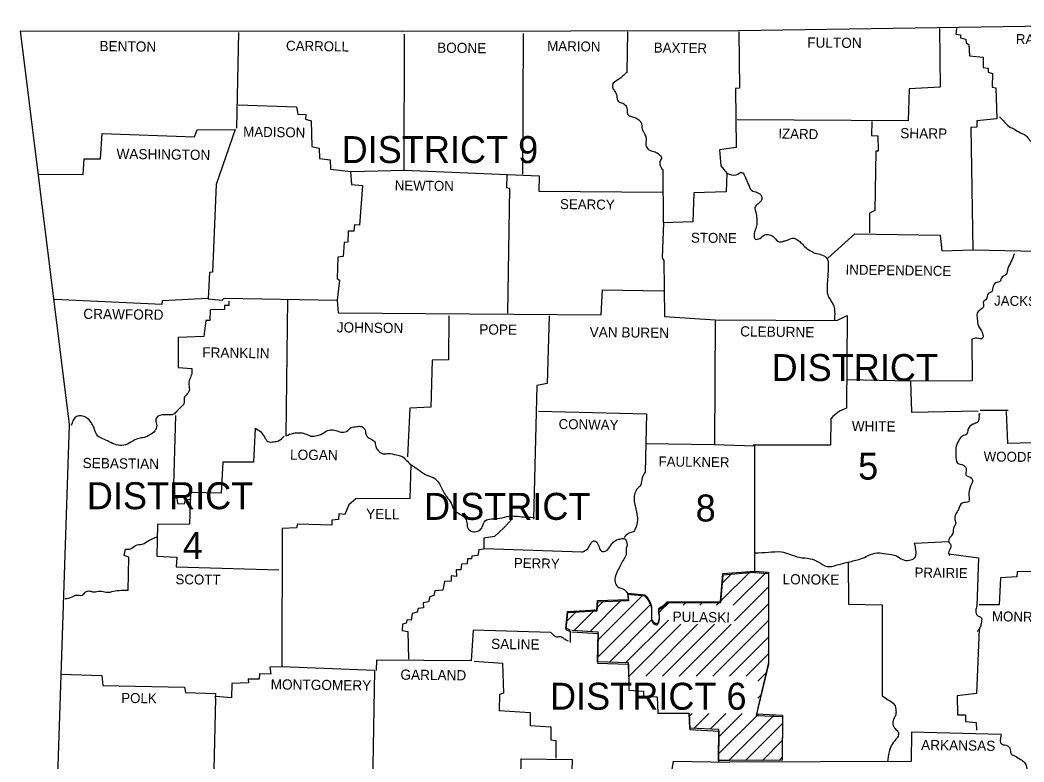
# Model space of a CAD drawing. Extents: x 76 to 6945, y -3933 to 2152.
# Drawn here: x 5012.1 to 5436, y -2002.1 to -1688.7 of the extents above; entities that cross this region are included whole.
import ezdxf

# ---------------------------------------------------------------- set-up
doc = ezdxf.new("R2010")
doc.units = 0
doc.layers.add('R_Draft', color=7, linetype='Continuous')

msp = doc.modelspace()

# ---------------------------------------------------------------- linework, layer by layer
at = {"layer": 'R_Draft'}
for p, q in [((5417.49, -1853.41), (5429.39, -1853.41)), ((5161.79, -1963.41), (5160.63, -2026.21))]:
    msp.add_line(p, q, dxfattribs=at)
for points in [[(5012.09, -1693.31), (5173.79, -1693.41), (5315.69, -1693.11), (5483.09, -1690.51), (5560.69, -1688.71)], [(5012.09, -1693.31), (5032.79, -1859.51), (5023.79, -2130.81)], [(5104.39, -1693.91), (5103.49, -1734.41)], [(5104.19, -1724.51), (5128.79, -1725.31), (5129.39, -1728.51), (5132.79, -1728.61), (5132.69, -1730.61), (5135.09, -1731.21), (5135.29, -1742.11), (5138.39, -1742.81), (5138.59, -1747.11), (5142.99, -1747.71), (5143.19, -1751.71), (5151.89, -1752.61), (5174.29, -1752.11), (5174.49, -1694.61)], [(5224.59, -1694.41), (5224.29, -1753.81)], [(5268.59, -1693.71), (5268.39, -1710.81)], [(5315.69, -1693.71), (5315.89, -1717.51), (5314.19, -1717.61), (5314.49, -1742.51), (5307.49, -1743.51), (5308.09, -1750.21), (5310.49, -1753.31), (5310.29, -1761.21), (5296.69, -1761.71), (5296.19, -1773.91), (5283.79, -1774.31), (5283.19, -1789.11), (5283.89, -1790.31), (5284.19, -1813.91), (5305.59, -1815.31), (5305.29, -1868.01), (5322.29, -1868.51), (5322.29, -1922.11), (5308.89, -1923.11), (5307.89, -1934.91), (5285.39, -1935.01)], [(5400.39, -1692.21), (5400.59, -1717.01), (5387.59, -1717.71), (5387.19, -1731.31), (5314.89, -1730.91)], [(5407.59, -1692.31), (5407.29, -1694.71), (5409.29, -1695.01), (5409.19, -1696.21), (5411.49, -1696.71), (5411.69, -1698.31), (5412.79, -1699.01), (5413.09, -1703.81), (5418.79, -1704.41), (5418.79, -1708.71), (5420.89, -1709.01), (5420.89, -1710.71), (5422.69, -1711.21), (5422.59, -1717.01), (5424.19, -1717.31), (5424.59, -1730.41), (5416.09, -1731.21), (5416.19, -1734.01), (5413.59, -1734.11), (5414.49, -1785.71), (5454.79, -1786.61), (5455.49, -1866.81), (5429.19, -1867.51), (5428.69, -1854.01)], [(5371.79, -1731.61), (5371.59, -1737.41), (5374.39, -1737.61), (5374.49, -1744.01), (5373.49, -1744.01), (5373.09, -1769.21), (5370.79, -1770.21), (5370.79, -1778.61)], [(5019.99, -1753.81), (5038.69, -1753.91), (5039.19, -1747.31), (5046.09, -1747.31), (5046.69, -1736.61), (5085.69, -1738.01), (5086.89, -1735.01), (5102.99, -1734.91), (5094.89, -1758.11), (5093.29, -1795.21), (5092.09, -1795.31), (5091.49, -1806.51), (5097.39, -1807.01), (5098.29, -1806.11), (5145.99, -1807.01), (5146.49, -1812.31)], [(5151.69, -1752.81), (5152.09, -1758.21), (5156.69, -1758.51), (5155.49, -1775.31), (5153.39, -1775.21), (5152.99, -1777.91), (5150.59, -1777.91), (5150.49, -1782.51), (5148.99, -1782.61), (5148.49, -1788.51), (5146.29, -1788.81), (5145.99, -1797.81), (5146.99, -1798.51), (5145.99, -1807.01)], [(5174.29, -1752.11), (5231.29, -1754.51), (5231.19, -1761.01), (5283.49, -1761.41)], [(5217.59, -1754.21), (5217.49, -1759.41), (5218.79, -1759.71), (5217.99, -1812.51)], [(5283.79, -1774.31), (5283.69, -1751.81)], [(5353.19, -1789.31), (5364.59, -1779.01), (5400.59, -1779.51), (5401.29, -1786.21), (5414.39, -1785.71)], [(5146.49, -1812.31), (5257.49, -1813.21), (5257.99, -1802.71), (5283.79, -1803.01)], [(5026.59, -1806.61), (5072.09, -1808.71), (5072.29, -1807.11), (5091.29, -1806.21)], [(5100.29, -1807.41), (5100.29, -1809.21), (5098.39, -1809.21), (5098.49, -1811.01), (5092.39, -1811.11), (5092.29, -1815.61), (5090.59, -1815.61), (5089.69, -1822.31), (5078.89, -1822.81), (5078.79, -1835.51), (5084.59, -1835.91)], [(5124.99, -1806.61), (5124.29, -1864.31)], [(5193.12, -1813.57), (5193.02, -1832.27), (5186.12, -1832.37), (5185.52, -1852.27), (5176.72, -1852.57), (5175.72, -1873.17)], [(5235.48, -1813.68), (5234.74, -1842.28), (5230.35, -1843.01), (5228.88, -1899.47)], [(5305.59, -1815.31), (5356.99, -1815.61), (5361.39, -1813.51), (5361.09, -1852.61), (5358.09, -1853.91), (5355.39, -1856.21), (5354.49, -1857.11), (5354.39, -1868.31), (5321.69, -1868.31)], [(5413.99, -1823.51), (5414.19, -1841.11), (5388.19, -1841.21), (5361.49, -1840.71)], [(5388.19, -1841.21), (5388.59, -1854.31), (5416.69, -1853.81)], [(5077.79, -1855.71), (5076.79, -1890.11), (5078.29, -1890.51), (5078.59, -1892.91), (5081.59, -1893.11), (5081.89, -1891.41), (5084.29, -1891.01)], [(5230.99, -1853.91), (5276.69, -1855.01), (5276.09, -1879.71)], [(5417.49, -1855.11), (5416.99, -1855.21)], [(5111.39, -1861.11), (5110.69, -1875.41), (5097.69, -1875.51), (5096.99, -1888.51), (5084.09, -1888.21), (5083.69, -1901.61), (5070.19, -1901.71), (5069.79, -1915.11), (5078.29, -1915.61), (5077.99, -1919.71), (5121.39, -1920.91)], [(5276.19, -1867.61), (5305.29, -1868.01)], [(5455.49, -1866.81), (5456.99, -1921.61), (5433.19, -1921.71), (5433.09, -1923.91), (5426.19, -1924.31), (5425.59, -1935.71), (5417.19, -1935.71)], [(5177.09, -1876.41), (5176.69, -1890.81), (5153.89, -1890.91), (5150.89, -1893.51), (5149.19, -1897.51), (5146.69, -1897.31), (5146.59, -1899.61), (5143.69, -1899.91), (5143.79, -1902.01), (5129.29, -1901.61), (5128.79, -1903.21), (5122.79, -1903.41), (5122.59, -1961.76)], [(5219.99, -1899.21), (5216.39, -1903.11), (5212.49, -1906.81), (5207.99, -1907.51), (5207.99, -1912.21), (5205.79, -1912.51), (5205.39, -1914.91), (5202.89, -1915.11), (5202.69, -1916.21), (5200.99, -1916.31), (5200.89, -1918.41), (5198.49, -1918.51), (5198.29, -1920.91), (5196.29, -1920.91), (5196.39, -1923.71), (5194.19, -1923.51), (5194.09, -1925.71), (5191.39, -1925.91), (5190.59, -1929.51), (5187.19, -1929.81), (5186.89, -1931.81), (5185.09, -1932.31), (5184.59, -1934.41), (5182.29, -1934.91), (5182.49, -1937.01), (5180.19, -1937.21), (5179.79, -1938.81), (5177.69, -1939.41), (5177.19, -1942.11), (5175.59, -1942.01), (5175.09, -1943.41), (5173.59, -1943.91), (5173.49, -1946.61), (5175.79, -1947.01), (5176.19, -1958.61)], [(5389.79, -1909.71), (5404.29, -1909.01)], [(5057.69, -1929.61), (5057.99, -1915.51), (5055.99, -1914.91), (5056.59, -1912.21)], [(5249.29, -1913.41), (5208.09, -1912.11)], [(5404.29, -1914.21), (5416.79, -1915.81), (5416.09, -1936.21)], [(5361.79, -1917.51), (5361.99, -1935.41), (5376.09, -1935.71), (5376.19, -1974.11)], [(5285.39, -1934.41), (5307.89, -1934.31), (5308.89, -1922.51), (5322.29, -1921.51)], [(5307.89, -1934.21), (5320.49, -1921.61)], [(5308.59, -1926.51), (5312.89, -1922.21)], [(5313.29, -1935.91), (5327.29, -1921.91)], [(5322.29, -1921.51), (5328.09, -1921.91), (5328.19, -1960.11), (5323.59, -1979.21)], [(5322.29, -1922.11), (5328.09, -1922.51), (5328.19, -1960.71), (5322.99, -1982.41), (5334.09, -1982.91), (5333.99, -2001.31)], [(5313.59, -1942.61), (5328.09, -1928.11)], [(5244.39, -1946.51), (5244.39, -1946.41), (5242.59, -1945.51), (5243.29, -1938.51), (5255.59, -1937.81), (5255.99, -1933.91), (5269.09, -1933.41), (5268.79, -1930.71), (5275.99, -1931.51)], [(5275.99, -1932.11), (5268.79, -1931.31), (5269.09, -1934.01), (5255.99, -1934.51), (5255.59, -1938.41), (5243.29, -1939.11), (5242.59, -1946.11), (5244.39, -1947.01), (5244.39, -1951.61)], [(5256.19, -1950.51), (5275.19, -1931.51)], [(5252.79, -1946.91), (5266.09, -1933.61)], [(5255.69, -1936.91), (5258.79, -1933.81)], [(5255.89, -1957.91), (5278.39, -1935.51)], [(5281.89, -1939.01), (5286.49, -1934.41)], [(5292.09, -1935.91), (5293.59, -1934.41)], [(5297.59, -1965.81), (5328.09, -1935.21)], [(5299.19, -1935.91), (5300.59, -1934.41)], [(5306.19, -1935.91), (5307.69, -1934.41)], [(5242.89, -1942.71), (5247.39, -1938.21)], [(5246.09, -1946.51), (5254.89, -1937.71)], [(5260.99, -1959.91), (5279.09, -1941.81)], [(5267.79, -1960.21), (5285.89, -1942.11)], [(5269.19, -1965.91), (5269.29, -1965.81), (5291.19, -1943.91)], [(5276.29, -1965.81), (5298.19, -1943.91)], [(5283.39, -1965.81), (5305.29, -1943.91)], [(5290.49, -1965.81), (5312.39, -1943.91)], [(5304.59, -1965.81), (5328.09, -1942.31)], [(5417.19, -1945.81), (5415.99, -1973.21), (5407.79, -1974.11), (5407.99, -1982.21), (5411.29, -1982.11), (5411.39, -1984.91), (5415.89, -1985.41), (5415.99, -1988.71)], [(5236.19, -1947.41), (5203.49, -1946.41), (5202.59, -1959.31), (5162.59, -1959.11), (5162.43, -1963.43)], [(5269.19, -1965.81), (5268.99, -1960.21), (5255.89, -1959.71), (5256.29, -1947.21), (5245.09, -1946.51)], [(5245.09, -1947.11), (5256.29, -1947.81), (5255.89, -1960.31), (5268.99, -1960.81), (5269.19, -1971.71), (5275.39, -1972.21), (5275.39, -1974.11), (5281.19, -1974.51), (5281.39, -1981.51), (5294.59, -1981.51), (5294.99, -1988.41), (5307.19, -1989.01), (5307.09, -2002.01)], [(5311.69, -1965.81), (5328.09, -1949.31)], [(5318.79, -1965.81), (5328.09, -1956.41)], [(5122.59, -1961.76), (5122.59, -1961.91), (5117.59, -1962.01), (5117.99, -1965.01), (5113.19, -1964.91), (5113.09, -1967.11), (5108.39, -1967.11), (5108.49, -1968.71), (5101.49, -1968.91), (5101.39, -1975.01), (5094.6, -1974.41)], [(5161.79, -1963.41), (5122.59, -1961.91)], [(5203.79, -1959.51), (5215.89, -1960.41), (5216.29, -1973.01), (5214.59, -1973.61), (5214.39, -1980.31), (5227.49, -1981.21), (5227.49, -1986.71), (5236.19, -1987.21), (5236.29, -1992.71), (5238.39, -1993.01), (5238.29, -2000.41)], [(5029.29, -1965.01), (5046.59, -1965.61), (5046.99, -1969.81), (5081.59, -1970.51), (5081.99, -1972.71), (5094.59, -1973.11), (5094.49, -1975.01)], [(5323.59, -1968.01), (5327.09, -1964.51)], [(5094.58, -1975.18), (5093.5, -2023.41)], [(5323.59, -1975.11), (5324.89, -1973.81)], [(5307.09, -2001.41), (5307.19, -1988.41), (5294.99, -1987.81), (5294.69, -1981.61)], [(5294.79, -1982.71), (5295.89, -1981.61)], [(5296.69, -1987.91), (5302.99, -1981.61)], [(5303.49, -1988.21), (5310.09, -1981.61)], [(5307.09, -1998.61), (5323.89, -1981.91)], [(5307.19, -1991.51), (5317.09, -1981.61)], [(5311.39, -2001.51), (5330.69, -1982.11)], [(5323.09, -1981.61), (5322.99, -1981.81), (5334.09, -1982.31), (5333.99, -2000.71)], [(5318.49, -2001.51), (5333.99, -1985.91)], [(5426.39, -1990.51), (5388.59, -1989.51), (5388.39, -2001.81), (5311.89, -2002.11)], [(5325.59, -2001.41), (5333.99, -1993.01)], [(5160.79, -2017.41), (5217.99, -2018.21), (5219.09, -2008.71), (5223.59, -2008.71), (5223.69, -2000.71), (5245.29, -2001.01), (5245.09, -2005.81), (5250.69, -2006.21), (5250.69, -2015.01), (5254.29, -2015.31), (5254.25, -2016.22)], [(5332.69, -2001.41), (5333.99, -2000.01)], [(5254.29, -2015.31), (5259.89, -2014.51), (5260.29, -2011.11), (5263.59, -2010.51), (5263.79, -2008.51), (5287.09, -2007.81), (5287.99, -2001.71), (5311.89, -2002.11)], [(5311.89, -2001.51), (5307.09, -2001.41)], [(5333.99, -2001.31), (5311.89, -2001.51)]]:
    msp.add_lwpolyline(points, dxfattribs=at)
for points in [[(5268.39, -1710.81), (5266.59, -1712.31), (5264.99, -1713.71), (5262.59, -1715.41), (5262.29, -1717.01), (5263.09, -1718.61), (5263.89, -1719.91), (5264.19, -1721.71), (5264.89, -1723.21), (5266.59, -1723.81), (5267.99, -1725.11), (5268.49, -1726.91), (5268.69, -1728.61), (5270.29, -1729.41), (5272.09, -1730.01), (5273.79, -1731.21), (5274.59, -1732.71), (5274.79, -1734.61), (5275.49, -1736.11), (5276.29, -1737.91), (5276.49, -1739.41), (5276.29, -1740.91), (5276.69, -1742.31), (5277.99, -1743.71), (5280.29, -1744.41), (5281.89, -1745.41), (5282.99, -1746.81), (5282.29, -1748.51), (5282.39, -1750.01), (5283.29, -1751.81)], [(5425.69, -1729.51), (5427.89, -1731.81), (5429.79, -1733.71), (5431.99, -1734.81), (5434.59, -1736.31), (5436.89, -1737.51), (5438.39, -1739.41), (5440.49, -1741.51), (5442.59, -1743.21), (5445.89, -1744.81), (5446.99, -1746.51), (5448.49, -1748.61), (5450.09, -1745.91)], [(5310.49, -1753.31), (5314.49, -1754.01), (5316.89, -1753.11), (5318.59, -1755.71), (5319.49, -1757.71), (5320.99, -1760.61), (5323.39, -1761.51), (5325.19, -1763.11), (5325.19, -1764.81), (5323.59, -1766.41), (5322.39, -1768.01), (5322.79, -1769.91), (5323.19, -1772.51), (5323.19, -1775.01), (5322.59, -1777.31), (5322.09, -1779.41), (5322.59, -1781.21), (5324.49, -1780.91), (5326.49, -1779.41), (5328.59, -1779.41), (5330.59, -1780.51), (5332.69, -1782.41), (5334.79, -1782.01), (5336.49, -1781.51), (5338.89, -1780.81), (5340.59, -1781.71), (5342.09, -1782.91), (5343.89, -1784.81), (5345.59, -1786.01), (5347.79, -1787.11), (5350.49, -1787.81), (5352.99, -1789.51), (5353.39, -1792.41), (5353.29, -1794.91), (5353.09, -1798.01), (5352.89, -1801.41), (5353.19, -1804.71), (5354.29, -1806.91), (5355.69, -1809.51), (5356.09, -1811.91), (5355.99, -1815.71)], [(5431.89, -1787.51), (5430.69, -1790.61), (5429.29, -1793.61), (5428.39, -1796.21), (5426.49, -1797.71), (5425.89, -1799.11), (5424.19, -1799.71), (5422.89, -1801.71), (5422.29, -1803.51), (5420.89, -1804.31), (5420.19, -1806.51), (5418.89, -1807.71), (5418.99, -1809.71), (5417.49, -1811.11), (5416.29, -1812.71), (5416.29, -1814.91), (5416.79, -1817.81), (5417.79, -1819.51), (5418.69, -1821.71), (5418.59, -1823.11), (5416.09, -1823.11), (5413.99, -1823.51)], [(5084.59, -1835.91), (5084.59, -1838.01), (5083.79, -1840.21), (5083.29, -1842.11), (5083.59, -1844.61), (5082.69, -1846.61), (5081.39, -1848.21), (5081.39, -1850.21), (5079.89, -1852.31), (5078.29, -1853.91), (5076.89, -1855.21), (5074.39, -1855.41), (5072.29, -1855.51), (5070.19, -1856.21), (5069.39, -1857.71), (5069.79, -1860.01), (5068.99, -1862.21), (5066.89, -1863.91), (5064.59, -1865.01), (5062.19, -1865.41), (5058.89, -1867.01), (5055.89, -1868.31), (5052.69, -1868.11), (5049.69, -1866.81), (5046.99, -1865.61), (5044.89, -1864.41), (5043.19, -1860.71), (5042.09, -1858.71), (5040.19, -1856.71), (5037.89, -1855.91), (5035.99, -1856.11), (5033.69, -1860.01)], [(5416.99, -1855.21), (5416.49, -1858.51), (5414.59, -1859.41), (5412.39, -1861.61), (5411.89, -1863.61), (5410.09, -1864.41), (5408.39, -1866.51), (5407.29, -1869.41), (5407.29, -1872.41), (5407.99, -1875.81), (5410.49, -1876.71), (5411.69, -1878.71), (5411.49, -1880.81), (5413.89, -1882.21), (5414.29, -1883.41), (5413.89, -1884.71), (5412.79, -1888.41), (5412.89, -1890.91), (5412.69, -1892.01), (5409.99, -1892.71), (5408.39, -1895.41), (5407.29, -1897.31), (5406.89, -1899.81), (5407.19, -1901.61), (5406.39, -1903.01), (5406.09, -1905.11), (5405.09, -1906.91), (5404.19, -1908.61), (5405.19, -1910.61), (5404.89, -1912.01), (5404.29, -1914.21), (5404.79, -1914.91)], [(5124.29, -1864.31), (5127.59, -1863.21), (5129.99, -1863.01), (5132.39, -1863.41), (5134.89, -1864.41), (5137.59, -1864.21), (5139.59, -1863.51), (5141.59, -1862.21), (5143.79, -1861.81), (5145.89, -1862.21), (5148.09, -1862.81), (5150.49, -1862.11), (5151.89, -1860.81), (5154.29, -1860.41), (5156.39, -1860.41), (5157.89, -1862.11), (5158.19, -1863.91), (5160.09, -1865.61), (5161.79, -1866.71), (5162.29, -1868.81), (5163.19, -1870.31), (5164.09, -1871.31), (5165.39, -1871.91), (5167.59, -1871.71), (5170.99, -1872.41), (5173.19, -1872.91), (5175.19, -1874.61), (5177.09, -1876.41)], [(5111.39, -1861.11), (5113.59, -1862.51), (5115.29, -1864.81), (5116.79, -1866.71), (5119.29, -1866.81), (5121.29, -1866.41), (5123.59, -1864.41)], [(5177.09, -1876.41), (5180.59, -1878.81), (5183.89, -1880.91), (5187.29, -1882.41), (5189.19, -1884.61), (5190.89, -1888.01), (5192.29, -1890.11), (5194.09, -1892.71), (5195.39, -1895.61), (5197.49, -1897.21), (5199.69, -1898.61), (5200.79, -1901.11), (5201.29, -1903.61), (5203.69, -1904.81), (5205.99, -1904.31), (5207.29, -1902.81), (5208.49, -1900.21), (5211.19, -1899.41), (5214.69, -1899.11), (5218.69, -1898.21), (5223.09, -1898.41), (5229.29, -1898.81)], [(5276.09, -1879.71), (5274.79, -1882.01), (5274.19, -1885.01), (5272.59, -1886.91), (5271.59, -1889.11), (5271.49, -1892.01), (5271.99, -1894.61), (5272.49, -1897.11), (5272.89, -1899.41), (5272.39, -1902.31), (5271.09, -1904.81), (5269.09, -1905.51), (5267.19, -1907.21)], [(5056.59, -1912.21), (5058.79, -1912.01), (5060.89, -1910.61), (5063.69, -1910.01), (5066.49, -1908.51), (5069.99, -1906.91)], [(5249.29, -1913.41), (5251.79, -1912.01), (5253.09, -1909.91), (5254.69, -1908.61), (5256.29, -1910.41), (5257.69, -1913.01), (5259.19, -1913.01), (5261.09, -1911.21), (5262.29, -1909.61), (5263.79, -1908.41), (5265.39, -1907.91), (5267.09, -1907.71), (5268.39, -1909.61), (5267.99, -1912.61), (5267.99, -1914.61), (5266.89, -1916.71), (5265.69, -1918.91), (5264.39, -1921.41), (5263.39, -1924.11), (5263.59, -1926.71), (5264.99, -1928.41), (5266.59, -1928.91), (5268.79, -1931.11)], [(5322.49, -1913.71), (5328.09, -1913.51), (5333.59, -1913.31), (5337.09, -1914.31), (5341.09, -1915.61), (5345.79, -1916.21), (5349.09, -1917.51), (5352.99, -1919.51), (5357.99, -1918.61), (5361.89, -1917.61), (5366.99, -1916.31), (5370.29, -1914.91), (5374.09, -1913.71), (5377.89, -1914.21), (5382.19, -1915.01), (5384.89, -1916.61), (5389.79, -1915.91), (5389.79, -1909.71)], [(5057.69, -1929.61), (5054.79, -1929.71), (5051.49, -1930.11), (5048.49, -1930.51), (5045.79, -1930.01), (5043.29, -1930.41), (5041.59, -1930.01), (5039.49, -1930.51), (5038.29, -1931.71), (5035.79, -1931.71), (5033.99, -1932.51), (5031.09, -1933.21)], [(5275.99, -1931.51), (5277.69, -1933.71), (5278.69, -1936.71), (5278.69, -1940.11), (5279.49, -1942.91), (5281.09, -1943.51), (5282.09, -1941.11), (5281.89, -1938.71), (5281.89, -1937.31), (5283.59, -1936.11), (5285.39, -1934.41)], [(5275.99, -1932.11), (5277.69, -1934.31), (5278.69, -1937.31), (5278.69, -1940.71), (5279.49, -1943.51), (5281.09, -1944.11), (5282.09, -1941.71), (5281.89, -1939.31), (5281.89, -1937.91), (5283.59, -1936.71), (5285.39, -1935.01)], [(5416.09, -1936.21), (5415.69, -1938.21), (5416.49, -1940.31), (5417.89, -1941.01), (5418.09, -1943.01), (5417.59, -1945.01), (5417.19, -1945.81), (5416.29, -1947.01)], [(5243.69, -1951.11), (5241.79, -1950.11), (5240.29, -1949.21), (5238.69, -1949.31), (5237.39, -1948.51), (5236.19, -1947.41)], [(5376.19, -1974.11), (5378.69, -1975.81), (5381.29, -1977.81), (5381.99, -1980.51), (5381.79, -1982.41), (5380.99, -1984.01), (5380.79, -1986.51), (5381.99, -1988.31), (5383.09, -1989.81), (5381.99, -1992.51), (5380.09, -1995.01), (5379.09, -1997.81), (5378.39, -2002.01)], [(5426.39, -1990.51), (5426.69, -1994.61), (5429.09, -1995.21), (5430.09, -1996.31), (5430.59, -1998.61), (5432.29, -1999.61), (5434.59, -2001.01), (5435.99, -2002.01), (5436.99, -2003.61), (5437.59, -2006.21), (5439.19, -2007.91), (5441.39, -2008.71), (5442.99, -2010.61), (5443.99, -2013.31), (5445.59, -2014.51), (5447.19, -2016.61), (5447.99, -2017.51), (5449.39, -2019.91), (5450.79, -2021.11), (5451.79, -2021.81), (5453.39, -2022.31), (5455.39, -2023.61), (5456.69, -2025.61), (5456.69, -2027.11), (5456.19, -2029.41), (5455.79, -2031.81), (5455.59, -2034.51), (5455.39, -2036.91), (5456.29, -2038.91), (5455.79, -2041.91), (5454.79, -2043.51), (5454.69, -2045.71), (5454.39, -2049.01), (5453.99, -2050.91), (5453.09, -2054.01), (5451.79, -2055.61)]]:
    msp.add_spline(points, degree=3, dxfattribs=at)

# ---------------------------------------------------------------- texts
for s, height, rotation, p in [('RANDOLPH', 4.201, 359.2583, (5432.59, -1698.81)), ('BENTON', 4.301, 359.2527, (5045.59, -1701.81)), ('CARROLL', 4.201, 359.1481, (5124.39, -1701.61)), ('BOONE', 4.301, 359.4001, (5188.19, -1702.51)), ('MARION', 4.201, 359.1854, (5234.69, -1701.71)), ('BAXTER', 4.201, 359.2559, (5279.69, -1702.41)), ('FULTON', 4.3, 359.4996, (5344.49, -1700.31)), ('MADISON', 4.201, 359.0906, (5106.29, -1737.91)), ('IZARD', 4.199, 358.9258, (5332.29, -1738.71)), ('SHARP', 4.3, 359.3905, (5383.79, -1738.61)), ('WASHINGTON', 4.3, 359.232, (5052.79, -1747.31)), ('NEWTON', 4.201, 359.2717, (5170.29, -1760.61)), ('SEARCY', 4.199, 359.2527, (5240.09, -1768.51)), ('STONE', 4.199, 359.4001, (5295.39, -1782.71)), ('INDEPENDENCE', 4.1993, 359.2187, (5360.69, -1796.21)), ('JACKSON', 4.199, 359.1352, (5423.39, -1809.31)), ('CRAWFORD', 4.299, 359.2771, (5038.79, -1814.91)), ('JOHNSON', 4.301, 359.3514, (5145.79, -1820.61)), ('POPE', 4.301, 359.6155, (5205.99, -1821.51)), ('VAN BUREN', 4.301, 359.3508, (5252.59, -1822.61)), ('CLEBURNE', 4.3, 359.2535, (5316.19, -1822.31)), ('FRANKLIN', 4.301, 359.1815, (5088.99, -1831.21)), ('CONWAY', 4.199, 359.0371, (5239.49, -1861.41)), ('WHITE', 4.301, 359.3139, (5363.29, -1862.31)), ('SEBASTIAN', 4.299, 359.2816, (5038.49, -1877.91)), ('LOGAN', 4.301, 359.3969, (5126.09, -1874.41)), ('FAULKNER', 4.201, 359.2486, (5281.69, -1877.21)), ('WOODRUFF', 4.199, 359.2748, (5418.99, -1875.11)), ('YELL', 4.301, 359.1987, (5158.19, -1899.41)), ('PERRY', 4.2, 359.0858, (5220.59, -1920.11)), ('PRAIRIE', 4.2, 359.2116, (5389.79, -1924.11)), ('SCOTT', 4.201, 359.4063, (5077.69, -1927.01)), ('LONOKE', 4.301, 359.4974, (5334.09, -1927.01)), ('PULASKI', 4.301, 359.053, (5287.59, -1942.81)), ('MONROE', 4.199, 359.0331, (5422.49, -1942.61)), ('SALINE', 4.301, 359.1491, (5210.99, -1954.31)), ('GARLAND', 4.301, 359.3658, (5172.69, -1967.31)), ('MONTGOMERY', 4.301, 359.2944, (5117.89, -1971.41)), ('POLK', 4.199, 359.2152, (5054.79, -1977.11)), ('ARKANSAS', 4.3, 359.2678, (5392.59, -1997.01))]:
    msp.add_text(s, height=height, rotation=rotation, dxfattribs=at).set_placement(p)
for s, p in [('DISTRICT 9', (5147.89, -1749.11)), ('DISTRICT', (5329.45, -1841.19)), ('5', (5365.99, -1882.81)), ('DISTRICT', (5040.29, -1895.31)), ('DISTRICT', (5182.69, -1899.81)), ('8', (5297.39, -1900.51)), ('4', (5080.79, -1916.31)), ('DISTRICT 6', (5235.89, -1980.01))]:
    msp.add_text(s, height=11.4, dxfattribs=at).set_placement(p)

doc.saveas('drawing.dxf')
